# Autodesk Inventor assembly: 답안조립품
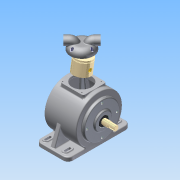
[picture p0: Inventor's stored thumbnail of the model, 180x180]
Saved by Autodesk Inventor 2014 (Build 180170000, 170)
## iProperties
Created: 2015-06
Part Number: 답안조립품
Document SubType Name: Assembly
Designer: Administrator
Author: Administrator
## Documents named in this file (13)
- C:\Users\Administrator\Desktop\450605V1033\답안조립품.iam
- C:\Users\Administrator\Desktop\450605V1033\1-본체.ipt
- C:\Users\Administrator\Desktop\450605V1033\베어링 6204.ipt
- C:\Users\Administrator\Desktop\450605V1033\메인커버.ipt
- C:\Users\Administrator\Desktop\450605V1033\오일실.ipt
- C:\Users\Administrator\Desktop\450605V1033\메인 크랭크 축-구동부.ipt
- C:\Users\Administrator\Desktop\450605V1033\크랭크 서브축.ipt
- C:\Users\Administrator\Desktop\450605V1033\베어링 NA 4902.ipt
- C:\Users\Administrator\Desktop\450605V1033\커넥팅 로드.ipt
- C:\Users\Administrator\Desktop\450605V1033\실린더.ipt
- C:\Users\Administrator\Desktop\450605V1033\실린더헤드.ipt
- C:\Users\Administrator\Desktop\450605V1033\피스톤 핀.ipt
- C:\Users\Administrator\Desktop\450605V1033\피스톤.ipt
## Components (3 placed, 3 different names)
1. 1-본체:1
2. 피스톤 핀:1
3. 피스톤:1
